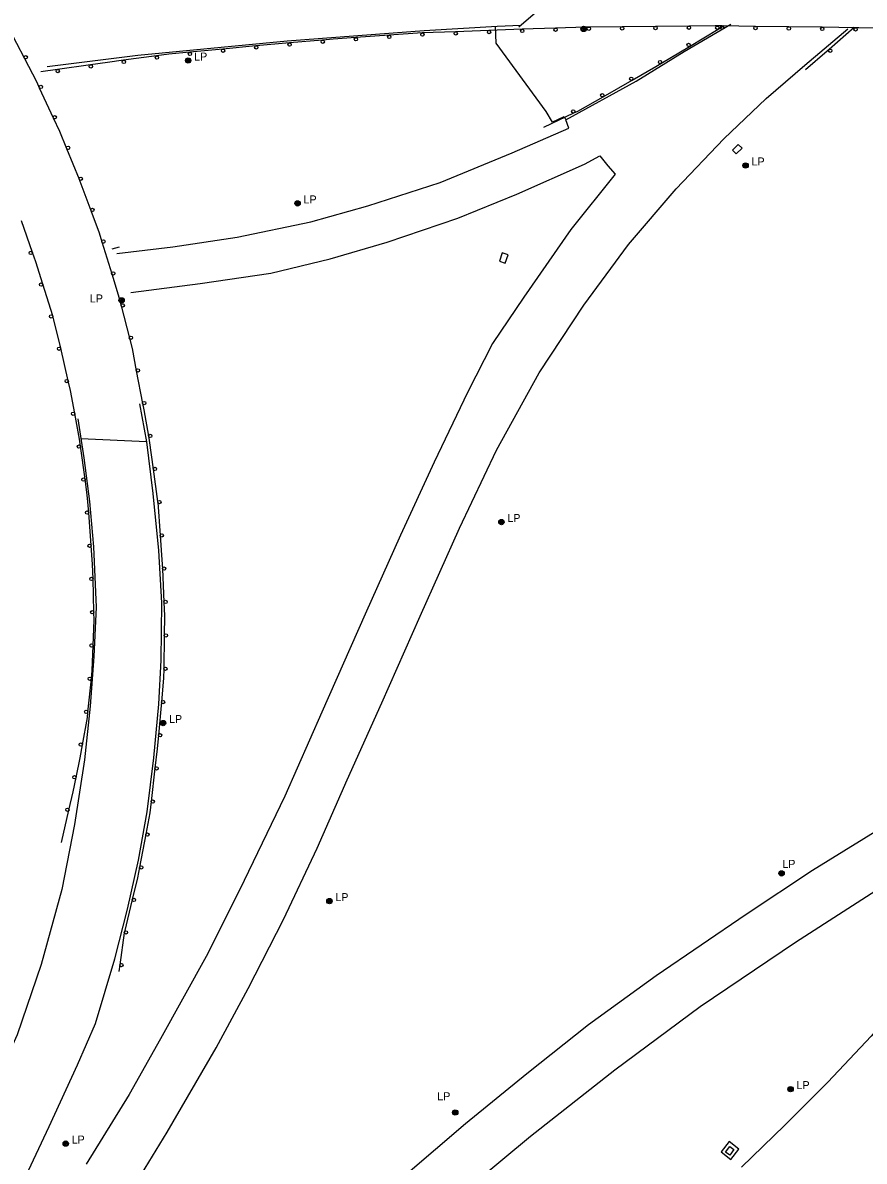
# Model space of a CAD drawing. Extents: x 2402803 to 2427059, y 6985292 to 6997652.
# Drawn here: x 2411260 to 2411764, y 6990960 to 6991642 of the extents above; entities that cross this region are included whole.
import ezdxf

# ---------------------------------------------------------------- set-up
doc = ezdxf.new("R2010")
doc.units = 0
for name, color, linetype in [('p_drainage conc drain', 7, 'Continuous'), ('p_drainage riprap', 7, 'Continuous'), ('p_road - paved curb', 7, 'Continuous'), ('p_road bridge end', 7, 'Continuous'), ('p_road guard rails', 7, 'Continuous'), ('p_utility manhole', 7, 'Continuous')]:
    doc.layers.add(name, color=color, linetype=linetype)

msp = doc.modelspace()

# ---------------------------------------------------------------- linework, layer by layer
at = {"layer": 'p_drainage conc drain'}
msp.add_lwpolyline([(2411683.33, 6990971.35), (2411678.42, 6990965.12), (2411684.26, 6990960.51), (2411689.17, 6990966.74)], close=True, dxfattribs=at)
at = {"layer": 'p_drainage riprap'}
msp.add_lwpolyline([(2411585.65, 6991584.05), (2411584.18, 6991585.86), (2411577.37, 6991582.55), (2411573.62, 6991588.95), (2411543.64, 6991629.87), (2411543.07, 6991640.11)], dxfattribs=at)
at = {"layer": 'p_road - paved curb'}
for points in [[(2411274.35, 6991615.93), (2411328.64, 6991622.74), (2411418.29, 6991631.34), (2411500.28, 6991637.6), (2411544.09, 6991640.17), (2411558.31, 6991640.78)], [(2411316.12, 6991503.83), (2411349.72, 6991507.77), (2411388.19, 6991513.66), (2411432.32, 6991522.85), (2411466.55, 6991532.44), (2411510.06, 6991546.35), (2411553.13, 6991564.1), (2411587.1, 6991578.94), (2411585.38, 6991583.9), (2411627.5, 6991607.12), (2411656.31, 6991625), (2411684.33, 6991641.44)], [(2411324.19, 6990941.05), (2411346.28, 6990977.02), (2411375.57, 6991027.54), (2411394.8, 6991063.1), (2411416.11, 6991104.4), (2411436.17, 6991147.33), (2411454.23, 6991188.24), (2411474.98, 6991234.39), (2411497.92, 6991286.31), (2411521.51, 6991339.15), (2411543.73, 6991385.8), (2411569.44, 6991432.18), (2411596.05, 6991472.82), (2411623.01, 6991509.27), (2411651.48, 6991542.65), (2411680.12, 6991572.68), (2411705.41, 6991596.76), (2411728.65, 6991616.8), (2411754.53, 6991638.48)], [(2411324.51, 6991480.43), (2411366.09, 6991485.77), (2411408.34, 6991492.08), (2411443.93, 6991500.62), (2411478.16, 6991510.69), (2411520.48, 6991525.06), (2411555.9, 6991539.43), (2411596.47, 6991557.35), (2411605.67, 6991562.4), (2411610.61, 6991556.31), (2411614.88, 6991551.46), (2411588.35, 6991518.17), (2411560.2, 6991477.69), (2411541.32, 6991449.87), (2411526.34, 6991420.55), (2411506.31, 6991378.75), (2411486.11, 6991334.9), (2411465.03, 6991287.64), (2411438.97, 6991228.71), (2411416.82, 6991178.39), (2411389.56, 6991122.14), (2411369.55, 6991082.18), (2411342.35, 6991032.86), (2411323.45, 6990999.57), (2411297.7, 6990957.8)], [(2411261.59, 6990950.64), (2411275.5, 6990980.29), (2411292.54, 6991017.31), (2411303.22, 6991042.14), (2411314.94, 6991080.79), (2411322.48, 6991110.69), (2411329.05, 6991140.05), (2411334.32, 6991168.94), (2411338.28, 6991201.33), (2411341.19, 6991233.66), (2411342.69, 6991259.91), (2411342.99, 6991294.4), (2411341.3, 6991325.73), (2411337.83, 6991359.94), (2411333.97, 6991390.84), (2411329.82, 6991413.74)], [(2411489.28, 6990951.3), (2411525.07, 6990982.17), (2411562, 6991012.17), (2411598.93, 6991041.59), (2411639.48, 6991070.85), (2411693.43, 6991107.75), (2411733.35, 6991133.96), (2411782.84, 6991164.69), (2411838.75, 6991197.51), (2411893.4, 6991227.67), (2411934.03, 6991249.22), (2412008.17, 6991286.5), (2412060.9, 6991311.56), (2412113.17, 6991334.87), (2412158.67, 6991354.26), (2412219.5, 6991378.25), (2412283.56, 6991401.82), (2412323.52, 6991415.97)], [(2411292.68, 6991404.67), (2411296.33, 6991381.24), (2411299.65, 6991355.19), (2411302.12, 6991327.85), (2411303.65, 6991291.73), (2411302.38, 6991262.26), (2411300.13, 6991232.29), (2411296.75, 6991200.15), (2411290.61, 6991161.39), (2411283.11, 6991122.4), (2411270.76, 6991077.56), (2411256.24, 6991035.24), (2411231.03, 6990979.94), (2411213.85, 6990947.13), (2411193.65, 6990909.98), (2411172.42, 6990871.23), (2411146.79, 6990824.72), (2411124.28, 6990785.3)], [(2411515.5, 6990934.14), (2411564.09, 6990974.47), (2411614.73, 6991014.35), (2411665.95, 6991052.36), (2411722.97, 6991090.95), (2411785.92, 6991131.15), (2411837.21, 6991161.8), (2411898.42, 6991195.19), (2411952.42, 6991223.32), (2412011.03, 6991252.63), (2412013.72, 6991247.44), (2411985.27, 6991229.87), (2411957.78, 6991211.1), (2411927.45, 6991190.17), (2411902.16, 6991169.52), (2411877.59, 6991148.7), (2411853.24, 6991125.42), (2411832.91, 6991105.55), (2411810.97, 6991082.74), (2411788.26, 6991057.63), (2411768.43, 6991034.6), (2411742.48, 6991006.93), (2411716.42, 6990980.99), (2411690.74, 6990956.01)]]:
    msp.add_lwpolyline(points, dxfattribs=at)
at = {"layer": 'p_road bridge end'}
for points in [[(2411557.07, 6991639.65), (2411604.19, 6991680.37)], [(2411294.5, 6991392.84), (2411333.95, 6991391.1)]]:
    msp.add_lwpolyline(points, dxfattribs=at)
for points in [[(2411685.29, 6991565.72), (2411688.75, 6991569.27), (2411691.03, 6991567.05), (2411687.57, 6991563.5)], [(2411547.19, 6991504.26), (2411545.46, 6991499.32), (2411549, 6991498.08), (2411550.73, 6991503.02)], [(2411681.12, 6990964.92), (2411683.67, 6990968.35), (2411686.16, 6990966.5), (2411683.61, 6990963.07)]]:
    msp.add_lwpolyline(points, close=True, dxfattribs=at)
at = {"layer": 'p_road guard rails'}
for p, q in [((2411251.35, 6991638.81), (2411260.55, 6991621.07)), ((2411519.25, 6991636.83), (2411499.26, 6991636.07)), ((2411539.23, 6991637.58), (2411519.25, 6991636.83)), ((2411579.16, 6991638.96), (2411559.21, 6991638.31)), ((2411619.11, 6991639.77), (2411599.12, 6991639.57)), ((2411639.1, 6991639.98), (2411619.11, 6991639.77)), ((2411659.09, 6991640.18), (2411639.1, 6991639.98)), ((2411659.5, 6991628.01), (2411676.65, 6991638.3)), ((2411676.65, 6991638.3), (2411680.33, 6991640.51)), ((2411699.08, 6991640.01), (2411679.08, 6991640.28)), ((2411719.08, 6991639.74), (2411699.08, 6991640.01)), ((2411739.07, 6991639.47), (2411719.08, 6991639.74)), ((2411759.07, 6991639.2), (2411739.07, 6991639.47)), ((2411758.32, 6991639.31), (2411743.24, 6991626.18)), ((2411419.55, 6991630.11), (2411399.64, 6991628.39)), ((2411439.47, 6991631.82), (2411419.55, 6991630.11)), ((2411479.33, 6991634.69), (2411459.39, 6991633.31)), ((2411642.36, 6991617.73), (2411659.5, 6991628.01)), ((2411339.96, 6991622.3), (2411320.15, 6991619.66)), ((2411379.74, 6991626.45), (2411359.83, 6991624.5)), ((2411300.35, 6991616.97), (2411280.55, 6991614.22)), ((2411280.55, 6991614.22), (2411270.44, 6991612.81)), ((2411607.66, 6991597.84), (2411625.03, 6991607.75)), ((2411269.6, 6991603.26), (2411277.98, 6991585.13)), ((2411572.13, 6991579.56), (2411590.19, 6991588.11)), ((2411285.92, 6991566.8), (2411293.52, 6991548.3)), ((2411265.42, 6991504.46), (2411258.85, 6991523.33)), ((2411307.11, 6991510.73), (2411313.01, 6991491.62)), ((2411313.26, 6991506.67), (2411317.58, 6991507.79)), ((2411277.65, 6991466.39), (2411271.62, 6991485.46)), ((2411318.61, 6991472.44), (2411323.59, 6991453.1)), ((2411286.98, 6991427.51), (2411282.4, 6991446.98)), ((2411327.74, 6991433.55), (2411331.49, 6991413.92)), ((2411297.08, 6991368.43), (2411294.3, 6991388.22)), ((2411300.72, 6991328.64), (2411299.19, 6991348.57)), ((2411340.58, 6991354.67), (2411342.05, 6991334.74)), ((2411343.37, 6991314.79), (2411344.26, 6991294.82)), ((2411302.36, 6991288.7), (2411301.82, 6991308.69)), ((2411344.46, 6991274.84), (2411344.17, 6991254.85)), ((2411298.73, 6991228.88), (2411300.83, 6991248.77)), ((2411342.82, 6991234.92), (2411341.04, 6991215.02)), ((2411338.95, 6991195.14), (2411336.63, 6991175.28)), ((2411282.85, 6991150.73), (2411287.38, 6991170.09)), ((2411333.42, 6991155.56), (2411329.74, 6991135.9)), ((2411325.33, 6991116.4), (2411320.58, 6991096.97)), ((2411317.86, 6991077.24), (2411317.33, 6991073.33))]:
    msp.add_line(p, q, dxfattribs=at)
for points in [[(2411499.26, 6991636.07), (2411499.16, 6991636.07), (2411479.33, 6991634.69)], [(2411559.21, 6991638.31), (2411554.22, 6991638.15), (2411539.23, 6991637.58)], [(2411599.12, 6991639.57), (2411597.3, 6991639.55), (2411579.16, 6991638.96)], [(2411679.08, 6991640.28), (2411674.79, 6991640.34), (2411659.09, 6991640.18)], [(2411779.06, 6991638.84), (2411761.01, 6991639.17), (2411759.07, 6991639.2)], [(2411399.64, 6991628.39), (2411399.5, 6991628.38), (2411379.74, 6991626.45)], [(2411459.39, 6991633.31), (2411445.71, 6991632.36), (2411439.47, 6991631.82)], [(2411359.83, 6991624.5), (2411347.19, 6991623.26), (2411339.96, 6991622.3)], [(2411743.24, 6991626.18), (2411742.06, 6991625.16), (2411728.96, 6991613.91)], [(2411260.55, 6991621.07), (2411268.06, 6991606.6), (2411269.6, 6991603.26)], [(2411320.15, 6991619.66), (2411310.44, 6991618.37), (2411300.35, 6991616.97)], [(2411625.03, 6991607.75), (2411639.38, 6991615.94), (2411642.36, 6991617.73)], [(2411590.19, 6991588.11), (2411592.61, 6991589.25), (2411607.66, 6991597.84)], [(2411277.98, 6991585.13), (2411281.7, 6991577.09), (2411285.92, 6991566.8)], [(2411293.52, 6991548.3), (2411293.96, 6991547.22), (2411300.47, 6991529.57)], [(2411300.47, 6991529.57), (2411305.44, 6991516.12), (2411307.11, 6991510.73)], [(2411271.62, 6991485.46), (2411267.41, 6991498.76), (2411265.42, 6991504.46)], [(2411313.01, 6991491.62), (2411316.92, 6991478.98), (2411318.61, 6991472.44)], [(2411282.4, 6991446.98), (2411278.37, 6991464.12), (2411277.65, 6991466.39)], [(2411323.59, 6991453.1), (2411325.18, 6991446.94), (2411327.74, 6991433.55)], [(2411290.87, 6991407.91), (2411288.34, 6991421.71), (2411286.98, 6991427.51)], [(2411331.49, 6991413.92), (2411332.21, 6991410.13), (2411335.09, 6991394.25)], [(2411294.3, 6991388.22), (2411293.71, 6991392.46), (2411290.87, 6991407.91)], [(2411335.09, 6991394.25), (2411335.55, 6991391.73), (2411337.91, 6991374.47)], [(2411337.91, 6991374.47), (2411340.55, 6991355.11), (2411340.58, 6991354.67)], [(2411299.19, 6991348.57), (2411298.38, 6991359.2), (2411297.08, 6991368.43)], [(2411342.05, 6991334.74), (2411343.13, 6991320.12), (2411343.37, 6991314.79)], [(2411301.82, 6991308.69), (2411301.58, 6991317.42), (2411300.72, 6991328.64)], [(2411344.26, 6991294.82), (2411344.63, 6991286.5), (2411344.46, 6991274.84)], [(2411301.92, 6991268.72), (2411302.49, 6991283.99), (2411302.36, 6991288.7)], [(2411300.83, 6991248.77), (2411301.36, 6991253.74), (2411301.92, 6991268.72)], [(2411344.17, 6991254.85), (2411344.09, 6991249.1), (2411342.82, 6991234.92)], [(2411295.41, 6991209.18), (2411298.39, 6991225.68), (2411298.73, 6991228.88)], [(2411341.04, 6991215.02), (2411340.3, 6991206.71), (2411338.95, 6991195.14)], [(2411291.64, 6991189.56), (2411294.03, 6991201.5), (2411295.41, 6991209.18)], [(2411287.38, 6991170.09), (2411289.92, 6991180.93), (2411291.64, 6991189.56)], [(2411336.63, 6991175.28), (2411335.84, 6991168.47), (2411333.42, 6991155.56)], [(2411329.74, 6991135.9), (2411328.53, 6991129.46), (2411325.33, 6991116.4)], [(2411320.58, 6991096.97), (2411320.47, 6991096.54), (2411317.86, 6991077.24)]]:
    msp.add_lwpolyline(points, dxfattribs=at)
for centre in [(2411499.3, 6991635.07), (2411519.29, 6991635.83), (2411539.27, 6991636.58), (2411559.24, 6991637.31), (2411579.19, 6991637.96), (2411599.13, 6991638.57), (2411619.12, 6991638.77), (2411639.11, 6991638.98), (2411659.1, 6991639.18), (2411676.13, 6991639.16), (2411679.07, 6991639.28), (2411699.07, 6991639.01), (2411719.06, 6991638.74), (2411739.06, 6991638.47), (2411759.06, 6991638.2), (2411399.73, 6991627.4), (2411419.64, 6991629.11), (2411439.55, 6991630.83), (2411459.46, 6991632.31), (2411479.4, 6991633.7), (2411658.99, 6991628.87), (2411261.44, 6991621.53), (2411340.1, 6991621.31), (2411359.93, 6991623.5), (2411379.83, 6991625.45), (2411743.89, 6991625.43), (2411300.48, 6991615.98), (2411320.28, 6991618.67), (2411641.84, 6991618.58), (2411280.69, 6991613.22), (2411624.53, 6991608.62), (2411270.51, 6991603.68), (2411607.16, 6991598.7), (2411589.77, 6991589.01), (2411278.89, 6991585.55), (2411286.85, 6991567.18), (2411294.44, 6991548.68), (2411301.41, 6991529.92), (2411308.06, 6991511.02), (2411264.48, 6991504.13), (2411313.97, 6991491.92), (2411270.67, 6991485.15), (2411319.58, 6991472.69), (2411276.7, 6991466.09), (2411324.56, 6991453.35), (2411281.43, 6991446.75), (2411328.72, 6991433.74), (2411286, 6991427.28), (2411332.47, 6991414.11), (2411289.89, 6991407.73), (2411293.31, 6991388.08), (2411336.08, 6991394.43), (2411338.9, 6991374.61), (2411296.09, 6991368.29), (2411341.58, 6991354.74), (2411298.2, 6991348.49), (2411343.05, 6991334.81), (2411299.72, 6991328.57), (2411344.37, 6991314.84), (2411300.82, 6991308.66), (2411345.26, 6991294.86), (2411301.36, 6991288.67), (2411345.46, 6991274.82), (2411300.92, 6991268.76), (2411345.17, 6991254.84), (2411299.84, 6991248.87), (2411343.82, 6991234.84), (2411297.73, 6991228.99), (2411342.04, 6991214.93), (2411294.43, 6991209.35), (2411339.94, 6991195.03), (2411290.66, 6991189.75), (2411286.41, 6991170.32), (2411337.63, 6991175.17), (2411334.4, 6991155.37), (2411330.72, 6991135.71), (2411326.3, 6991116.16), (2411321.55, 6991096.73), (2411318.85, 6991077.11)]:
    msp.add_circle(centre, 1, dxfattribs=at)
at = {"layer": 'p_utility manhole'}
for centre, radius in [((2411596.01, 6991638.49), 1.6), ((2411596.01, 6991638.49), 1.3), ((2411596.01, 6991638.49), 1), ((2411596.01, 6991638.49), 0.539), ((2411596.01, 6991638.49), 0.192), ((2411358.87, 6991619.55), 1.6), ((2411358.87, 6991619.55), 1.3), ((2411358.87, 6991619.55), 1), ((2411358.87, 6991619.55), 0.539), ((2411358.87, 6991619.55), 0.192), ((2411693.15, 6991556.6), 1.6), ((2411693.15, 6991556.6), 1.3), ((2411693.15, 6991556.6), 1), ((2411693.15, 6991556.6), 0.539), ((2411693.15, 6991556.6), 0.192), ((2411424.49, 6991533.84), 1.6), ((2411424.49, 6991533.84), 1.3), ((2411424.49, 6991533.84), 1), ((2411424.49, 6991533.84), 0.539), ((2411424.49, 6991533.84), 0.192), ((2411318.97, 6991475.71), 1.6), ((2411318.97, 6991475.71), 1.3), ((2411318.97, 6991475.71), 1), ((2411318.97, 6991475.71), 0.539), ((2411318.97, 6991475.71), 0.192), ((2411546.69, 6991342.8), 1.6), ((2411546.69, 6991342.8), 1.3), ((2411546.69, 6991342.8), 1), ((2411546.69, 6991342.8), 0.539), ((2411546.69, 6991342.8), 0.192), ((2411343.8, 6991222.26), 1.6), ((2411343.8, 6991222.26), 1.3), ((2411343.8, 6991222.26), 1), ((2411343.8, 6991222.26), 0.539), ((2411343.8, 6991222.26), 0.192), ((2411714.7, 6991132.12), 1.6), ((2411714.7, 6991132.12), 1.3), ((2411714.7, 6991132.12), 1), ((2411714.7, 6991132.12), 0.539), ((2411714.7, 6991132.12), 0.192), ((2411443.55, 6991115.48), 1.6), ((2411443.55, 6991115.48), 1.3), ((2411443.55, 6991115.48), 1), ((2411443.55, 6991115.48), 0.539), ((2411443.55, 6991115.48), 0.192), ((2411720.09, 6991002.74), 1.6), ((2411720.09, 6991002.74), 1.3), ((2411720.09, 6991002.74), 1), ((2411720.09, 6991002.74), 0.539), ((2411720.09, 6991002.74), 0.192), ((2411519.02, 6990988.72), 1.6), ((2411519.02, 6990988.72), 1.3), ((2411519.02, 6990988.72), 1), ((2411519.02, 6990988.72), 0.539), ((2411519.02, 6990988.72), 0.192), ((2411285.41, 6990970.09), 1.6), ((2411285.41, 6990970.09), 1.3), ((2411285.41, 6990970.09), 1), ((2411285.41, 6990970.09), 0.539), ((2411285.41, 6990970.09), 0.192)]:
    msp.add_circle(centre, radius, dxfattribs=at)

# ---------------------------------------------------------------- texts
for p in [(2411358.87, 6991619.55), (2411693.15, 6991556.6), (2411424.49, 6991533.84), (2411296.35, 6991474.47), (2411546.69, 6991342.8), (2411343.8, 6991222.26), (2411711.59, 6991135.42), (2411443.55, 6991115.48), (2411720.09, 6991002.74), (2411504.66, 6990996.08), (2411285.41, 6990970.09)]:
    msp.add_text('  LP', height=4.8, dxfattribs=at).set_placement(p)

doc.saveas('drawing.dxf')
